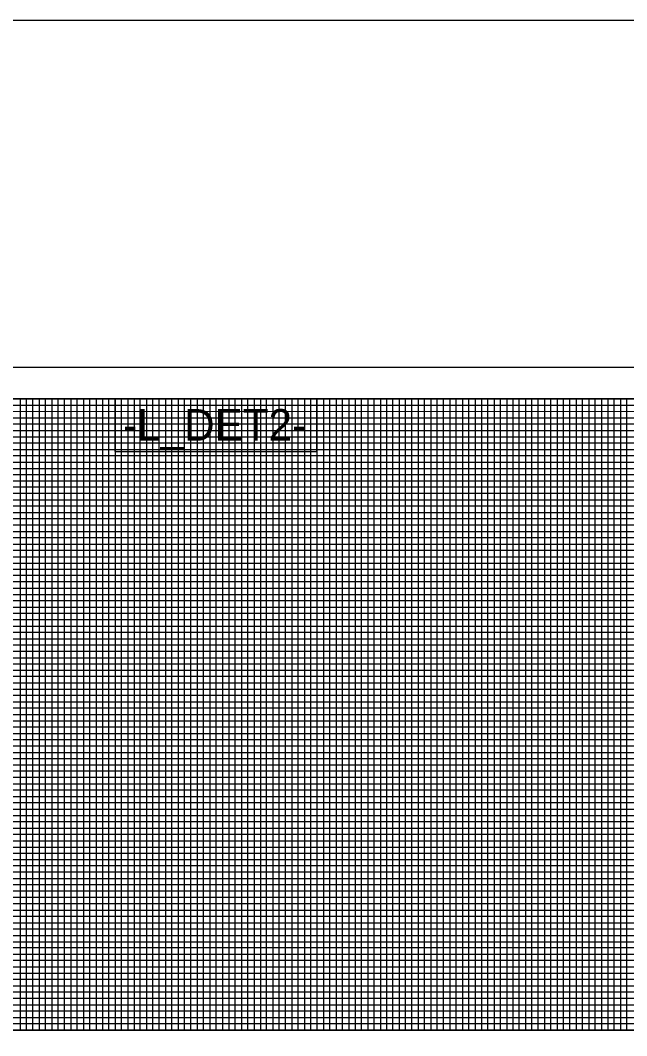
# Model space of a CAD drawing. Extents: x 505569 to 516904, y 436011 to 484484.
# Drawn here: x 506359 to 506839, y 483679 to 484484 of the extents above; entities that cross this region are included whole.
import ezdxf

# ---------------------------------------------------------------- set-up
doc = ezdxf.new("R2010")
doc.units = 0
for name, color, linetype in [('COGO Default Curve', 7, 'Continuous'), ('Exist Vertical Profile Ground Line', 7, 'Continuous'), ('Exist Vertical Profile Vertical Axis Label', 7, 'Continuous'), ('Old_Level_1', 7, 'Continuous'), ('Prop Grid Mask', 7, 'Continuous'), ('Prop Vertical Profile Curve Label', 7, 'Continuous'), ('Prop Vertical Profile Grade Label', 7, 'Continuous'), ('Scratch_Level_2', 7, 'Continuous')]:
    doc.layers.add(name, color=color, linetype=linetype)

msp = doc.modelspace()

# ---------------------------------------------------------------- linework, layer by layer
at = {"layer": 'COGO Default Curve'}
msp.add_line((505769.08, 484158.71), (507069.03, 484158.71), dxfattribs=at)
msp.add_line((505769.08, 484158.71), (507069.03, 484158.71), dxfattribs=at)
for points in [[(506344.08, 483683.71), (506394.08, 483683.71), (506394.08, 483683.71), (506394.08, 484183.71), (506444.08, 484183.71), (506444.08, 483683.71), (506494.08, 483683.71), (506494.08, 484183.71), (506544.08, 484183.71), (506544.08, 483683.71), (506594.08, 483683.71), (506594.08, 484183.71), (506644.08, 484183.71), (506644.08, 483683.71), (506694.08, 483683.71), (506694.08, 484183.71), (506744.08, 484183.71), (506744.08, 483683.71), (506794.08, 483683.71), (506794.08, 484183.71), (506844.08, 484183.71)], [(507069.08, 484108.71), (505769.08, 484108.71), (505769.08, 484058.71), (507069.08, 484058.71)], [(507269.08, 484008.71), (505769.08, 484008.71), (505769.08, 483958.71), (507094.08, 483958.71)], [(507269.08, 483908.71), (505769.08, 483908.71), (505769.08, 483858.71), (507269.08, 483858.71)], [(507269.08, 483808.71), (505769.08, 483808.71), (505769.08, 483758.71), (507269.08, 483758.71)], [(507269.08, 483708.71), (505769.08, 483708.71)]]:
    msp.add_lwpolyline(points, dxfattribs=at)
at = {"layer": 'Exist Vertical Profile Ground Line'}
msp.add_lwpolyline([(506593.73, 484183.71), (506433.86, 484183.71), (506433.86, 484142), (506593.73, 484142)], close=True, dxfattribs=at)
at = {"layer": 'Exist Vertical Profile Vertical Axis Label'}
for points in [[(506119.08, 484483.71), (507319.08, 484483.71), (507319.08, 483983.71), (507319.08, 483983.71), (507319.08, 483983.71), (506119.08, 483983.71)], [(505819.08, 484183.71), (505819.08, 483683.71), (507019.08, 483683.71), (507019.08, 483998.71), (507019.08, 484053.71), (507019.08, 484183.71)], [(505819.08, 484183.71), (507019.08, 484183.71), (507019.08, 483683.71), (507019.08, 483683.71), (507019.08, 483683.71), (505819.08, 483683.71)]]:
    msp.add_lwpolyline(points, close=True, dxfattribs=at)
at = {"layer": 'Prop Grid Mask'}
msp.add_lwpolyline([(505602.08, 483108.71), (507286.08, 483108.71), (507286.08, 484208.71), (505602.08, 484208.71)], close=True, dxfattribs=at)
at = {"layer": 'Prop Vertical Profile Curve Label'}
msp.add_line((505769.08, 483683.71), (507269.08, 483683.71), dxfattribs=at)
msp.add_lwpolyline([(507269.08, 484183.71), (505769.08, 484183.71), (505769.08, 483133.71), (507269.08, 483133.71)], close=True, dxfattribs=at)
at = {"layer": 'Prop Vertical Profile Grade Label'}
for p, q in [((505819.08, 484178.71), (507069.08, 484178.71)), ((507069.08, 484173.71), (505819.08, 484173.36)), ((505819.08, 484168.71), (507069.08, 484168.71)), ((507069.03, 484048.71), (505819.08, 484048.71)), ((507069.08, 484043.71), (505819.08, 484043.71)), ((507069.08, 484038.71), (505819.08, 484038.71)), ((505819.08, 484028.71), (507069.08, 484028.71)), ((507069.08, 484023.71), (505819.08, 484023.71)), ((505819.08, 484018.71), (507219.08, 484018.71)), ((507219.08, 483998.71), (505819.08, 483998.71)), ((505819.08, 483993.71), (507219.08, 483993.71)), ((507219.08, 483973.71), (505819.08, 483973.71)), ((505819.08, 483968.71), (507219.08, 483968.71)), ((507219.08, 483948.71), (505819.08, 483948.71)), ((505819.08, 483943.71), (507219.08, 483943.71)), ((507219.08, 483938.71), (505819.08, 483938.71)), ((505819.08, 483928.71), (507219.08, 483928.71)), ((507219.08, 483923.71), (505819.08, 483923.71)), ((505819.08, 483918.71), (507219.08, 483918.71)), ((507219.08, 483913.71), (505819.08, 483913.71)), ((505819.08, 483903.71), (507219.08, 483903.71)), ((507219.08, 483898.71), (505819.08, 483898.71)), ((505819.08, 483893.71), (507219.08, 483893.71)), ((507219.08, 483888.71), (505819.08, 483888.71)), ((505819.08, 483878.71), (507219.08, 483878.71)), ((507219.08, 483873.71), (505819.08, 483873.71)), ((505819.08, 483868.71), (507219.08, 483868.71)), ((507219.08, 483863.71), (505819.08, 483863.71)), ((505819.08, 483853.71), (507219.08, 483853.71)), ((507219.08, 483848.71), (505819.08, 483848.71)), ((505819.08, 483843.71), (507219.08, 483843.71)), ((507219.08, 483838.71), (505819.08, 483838.71)), ((505819.08, 483828.71), (507219.08, 483828.71)), ((507219.08, 483823.71), (505819.08, 483823.71)), ((505819.08, 483818.71), (507219.08, 483818.71)), ((507219.08, 483813.71), (505819.08, 483813.71)), ((505819.08, 483803.71), (507219.08, 483803.71)), ((507219.08, 483798.71), (505819.08, 483798.71)), ((507219.08, 483793.71), (505819.08, 483793.71)), ((507219.08, 483788.71), (505819.08, 483788.71)), ((505819.08, 483778.71), (507219.08, 483778.71)), ((507219.08, 483773.71), (505819.08, 483773.71)), ((505819.08, 483768.71), (507219.08, 483768.71)), ((507219.08, 483763.71), (505819.08, 483763.71)), ((505819.08, 483753.71), (507219.08, 483753.71)), ((507219.08, 483748.71), (505819.08, 483748.71)), ((505819.08, 483743.71), (507219.08, 483743.71)), ((507219.08, 483738.71), (505819.08, 483738.71)), ((505819.08, 483728.71), (507219.08, 483728.71)), ((507219.08, 483723.71), (505819.08, 483723.71)), ((505819.08, 483718.71), (507219.08, 483718.71)), ((507219.08, 483713.71), (505819.08, 483713.71)), ((505819.08, 483703.71), (507219.08, 483703.71)), ((507219.08, 483698.71), (505819.08, 483698.71)), ((505819.08, 483693.71), (507219.08, 483693.71))]:
    msp.add_line(p, q, dxfattribs=at)
for points in [[(506354.08, 484183.71), (506359.08, 484183.71), (506359.08, 483683.71), (506364.08, 483683.71), (506364.08, 484183.71), (506374.08, 484183.71), (506374.08, 483683.71), (506379.08, 483683.71), (506379.08, 484183.71), (506384.08, 484183.71), (506384.08, 483683.71), (506389.08, 483683.71), (506389.08, 484183.71), (506399.08, 484183.71), (506399.08, 483683.71), (506404.08, 483683.71), (506404.08, 484183.71), (506409.08, 484183.71), (506409.08, 483683.71), (506414.08, 483683.71), (506414.08, 484183.71), (506424.08, 484183.71), (506424.08, 483683.71), (506429.08, 483683.71), (506429.08, 484183.71), (506434.08, 484183.71), (506434.08, 483683.71), (506439.08, 483683.71), (506439.08, 484183.71), (506449.08, 484183.71), (506449.08, 483683.71), (506454.08, 483683.71), (506454.08, 484183.71), (506459.08, 484183.71), (506459.08, 483683.71), (506464.08, 483683.71), (506464.08, 484183.71), (506474.08, 484183.71), (506474.08, 483683.71), (506474.08, 483683.71), (506479.08, 483683.71), (506479.08, 484183.71), (506484.08, 484183.71), (506484.08, 483683.71), (506489.08, 483683.71), (506489.08, 484183.71), (506499.08, 484183.71), (506499.08, 483683.71), (506504.08, 483683.71), (506504.08, 484183.71), (506509.08, 484183.71), (506509.08, 483683.71), (506514.08, 483683.71), (506514.08, 484183.71), (506524.08, 484183.71), (506524.08, 483683.71), (506529.08, 483683.71), (506529.08, 484183.71), (506534.08, 484183.71), (506534.08, 483683.71), (506539.08, 483683.71), (506539.08, 484183.71), (506549.08, 484183.71), (506549.08, 483683.71), (506554.08, 483683.71), (506554.08, 484183.71), (506559.08, 484183.71), (506559.08, 483683.71), (506564.08, 483683.71), (506564.08, 484183.71), (506574.08, 484183.71), (506574.08, 483683.71), (506579.08, 483683.71), (506579.08, 484183.71), (506584.08, 484183.71), (506584.08, 483683.71), (506589.08, 483683.71), (506589.08, 484183.71), (506599.08, 484183.71), (506599.08, 483683.71), (506604.08, 483683.71), (506604.08, 484183.71), (506609.08, 484183.71), (506609.08, 483683.71), (506614.08, 483683.71), (506614.08, 484183.71), (506624.08, 484183.71), (506624.08, 483683.71), (506628.78, 483684.26), (506629.08, 483683.71), (506629.08, 484183.71), (506634.08, 484183.71), (506634.08, 483683.71), (506639.08, 483683.71), (506639.08, 484183.71), (506649.08, 484183.71), (506649.08, 483683.71), (506654.08, 483683.71)], [(506654.08, 483683.71), (506654.08, 484183.71), (506659.08, 484183.71), (506659.08, 483683.71), (506664.08, 483683.71), (506664.08, 484183.71), (506674.08, 484183.71), (506674.08, 483683.71), (506679.08, 483683.71), (506679.08, 484183.71), (506684.08, 484183.71), (506684.08, 483683.71), (506689.08, 483683.71), (506689.08, 484183.71), (506699.08, 484183.71), (506699.08, 483683.71), (506704.08, 483683.71), (506704.08, 484183.71), (506709.08, 484183.71), (506709.08, 483683.71), (506714.08, 483683.71), (506714.08, 484183.71), (506724.08, 484183.71), (506724.08, 483683.71), (506729.08, 483683.71), (506729.08, 484183.71), (506734.08, 484183.71), (506734.08, 483683.71), (506739.08, 483683.71), (506739.08, 484183.71), (506749.08, 484183.71), (506749.08, 483683.71), (506754.08, 483683.71), (506754.08, 484183.71), (506759.08, 484183.71), (506759.08, 483683.71), (506764.08, 483683.71), (506764.08, 484183.71), (506774.08, 484183.71), (506774.08, 483683.71), (506779.08, 483683.71), (506779.08, 484183.71), (506784.08, 484183.71), (506784.08, 483683.71), (506789.08, 483683.71), (506789.08, 484183.71), (506799.08, 484183.71), (506799.08, 483683.71), (506804.08, 483683.71), (506804.08, 484183.71), (506809.08, 484183.71), (506809.08, 483683.71), (506814.08, 483683.71), (506814.08, 484183.71), (506824.08, 484183.71), (506824.08, 483683.71), (506829.08, 483683.71), (506829.08, 484183.71), (506834.08, 484183.71), (506834.08, 483683.71), (506839.08, 483683.71), (506839.08, 484183.71), (506849.08, 484183.71)], [(507069.08, 484163.71), (505819.08, 484163.71), (505819.08, 484153.71), (507069.08, 484153.71)], [(507069.03, 484148.71), (505819.08, 484148.71), (505819.08, 484143.71), (507069.08, 484143.71)], [(507069.08, 484138.71), (505819.08, 484138.71), (505819.08, 484128.71), (507069.08, 484128.71)], [(507069.08, 484123.71), (505819.08, 484123.71), (505819.08, 484118.71), (507069.08, 484118.71)], [(507069.08, 484113.71), (505819.08, 484113.71), (505819.08, 484103.71), (507069.08, 484103.71)], [(507069.08, 484098.71), (505819.08, 484098.71), (505819.08, 484093.71), (507069.08, 484093.71)], [(507069.08, 484088.71), (505819.08, 484088.71), (505819.08, 484078.71), (507069.08, 484078.71)], [(507069.08, 484073.61), (505819.18, 484073.61), (505819.18, 484068.71), (507069.08, 484068.71)], [(507069.08, 484063.71), (505819.08, 484063.71), (505819.08, 484053.71), (507069.08, 484053.71)], [(507219.08, 484013.71), (505819.08, 484013.71), (505819.08, 484003.71), (507219.08, 484003.71)], [(507219.08, 483988.71), (505819.08, 483988.71), (505819.08, 483978.71), (507219.08, 483978.71)], [(507219.08, 483963.71), (505819.08, 483963.71), (505819.08, 483953.71), (507219.08, 483953.71)], [(507219.08, 483688.71), (505819.08, 483688.71)]]:
    msp.add_lwpolyline(points, dxfattribs=at)
at = {"layer": 'Scratch_Level_2'}
for points in [[(506319.08, 483683.71), (506369.08, 483683.71), (506369.08, 484183.71), (506419.08, 484183.71), (506419.08, 483683.71), (506469.08, 483683.71), (506469.08, 484183.71), (506519.08, 484183.71), (506519.08, 483683.71), (506569.08, 483683.71), (506569.08, 484183.71), (506619.08, 484183.71), (506619.08, 483683.71), (506669.08, 483683.71), (506669.08, 484183.71), (506719.08, 484183.71), (506719.08, 483683.71), (506769.08, 483683.71), (506769.08, 484183.71), (506819.08, 484183.71), (506819.08, 483683.71), (506869.08, 483683.71)], [(505769.08, 484133.71), (507069.08, 484133.71)], [(507069.08, 484083.71), (505769.08, 484083.71), (505769.08, 484033.71), (507069.08, 484033.71)], [(507269.08, 483983.71), (505769.08, 483983.71), (505769.08, 483933.71), (507269.08, 483933.71)], [(507269.08, 483883.71), (505769.08, 483883.71), (505769.08, 483833.71), (507269.08, 483833.71)], [(507269.08, 483783.71), (505769.08, 483783.71), (505769.08, 483783.71), (505769.08, 483733.71), (507269.08, 483733.71)]]:
    msp.add_lwpolyline(points, dxfattribs=at)

# ---------------------------------------------------------------- texts
at = {"layer": 'Old_Level_1'}
msp.add_text('-L_DET2-', height=25, dxfattribs=at).set_placement((506440.42, 484150.68))

doc.saveas('drawing.dxf')
